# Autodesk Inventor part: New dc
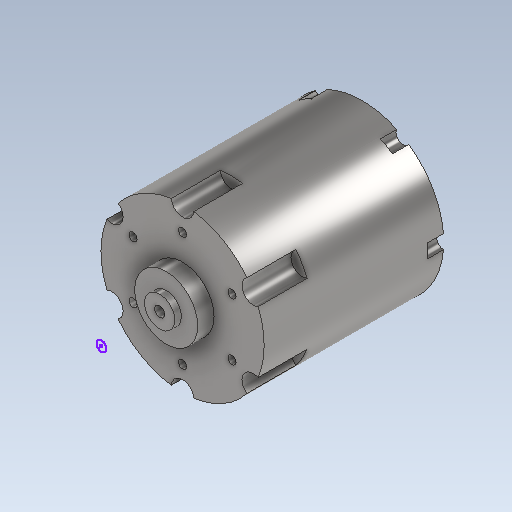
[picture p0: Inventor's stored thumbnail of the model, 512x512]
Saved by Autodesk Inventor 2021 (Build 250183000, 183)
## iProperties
Created: 2021-07
Part Number: New dc
Material: Steel, Mild
Document SubType Name: Sheet Metal
Designer: user
Density: 7.85 g/cm^3
Sheet Metal Rule: Default_mm
Appearance: Semi-Polished
Author: user
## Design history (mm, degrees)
sketch "Sketch1"
  geometry: C1 r 2.5 at (0, 0); 1 further point
  constraints: 1 centre point, 1 coincident
  dimensions: "d0" = 5 diameter of C1
extrude "Extrusion1" new body sketch "Sketch1" distance "d1" = 1.5; taper "d2" = 0 deg
sketch "Sketch2"
  geometry: C1 r 0.346 at (0, 2.5); C2 r 0.346 at (-2.165, 1.25); C3 r 0.346 at (-2.165, -1.25); C4 r 0.346 at (0, -2.5); C5 r 0.346 at (2.165, -1.25); C6 r 0.346 at (2.165, 1.25); 2 further points
  constraints: 6 centre point, 1 vertical alignment, 14 other
  dimensions: "d5" = 360 deg dimension on point (0, 0) C1.centre (derived)
cut "Cut1" sketch "Sketch2" dims "d8" = 0.5 (= Thickness), "d9" = 0
sketch "Sketch3"
  geometry: C1 r 0.125 at (0, 1.751); C2 r 0.125 at (1.516, 0.875); C3 r 0.125 at (1.516, -0.875); C4 r 0.125 at (0, -1.751); C5 r 0.125 at (-1.516, -0.875); C6 r 0.125 at (-1.516, 0.875); 1 further point
  constraints: 6 centre point, 13 other
  dimensions: "d10" = 0.25 diameter of C1; "d13" = 360 deg dimension on point (0, 0) C1.centre (derived)
cut "Cut2" sketch "Sketch3" dims "d7" = 0.5 (= Thickness), "d15" = 0.5 (= Thickness), "d16" = 0, "GapSize" = 0.5 (= Thickness), "SeamGap" = 0.01, "Thickness" = 0.5, "BendRadius" = 0.5 (= Thickness), "MinimumRemnant" = 1 (= 2 x Thickness), "BendReliefDepth" = 0.25 (= 0.5 x Thickness), "BendReliefWidth" = 0.5 (= Thickness), "CornerReliefSize" = 2 (= 4 x Thickness), "JacobiRadiusSize" = 0.5 (= BendRadius), "TransitionRadius" = 0.5 (= BendRadius)
sketch "Sketch4"
  geometry: C1 r 0.965 at (0, 0); 1 further point
  constraints: 1 centre point, 1 coincident
extrude "Extrusion2" join sketch "Sketch4" distance "d17" = 0.5; taper "d18" = 0 deg
sketch "Sketch5"
  geometry: C1 r 0.465 at (0, 0); 1 further point
  constraints: 1 centre point, 1 coincident
extrude "Extrusion3" join sketch "Sketch5" distance "d19" = 0.2; taper "d20" = 0 deg
sketch "Sketch6"
  geometry: C1 r 0.155 at (0, 0); 1 further point
  constraints: 1 centre point, 1 coincident
extrude "Extrusion4" join sketch "Sketch6" distance "d21" = 1.8; taper "d22" = 0 deg
sketch "Sketch7"
  geometry: C1 r 0.155 at (0, 0) reference; C2 r 2.5 at (0, 0); 1 further point
  constraints: 1 centre point, 1 coincident
extrude "Extrusion5" join sketch "Sketch7" distance "d23" = 2; taper "d24" = 0 deg
sketch "Sketch8"
  geometry: C1 r 0.155 at (0, 0) reference; C2 r 2.5 at (0, 0); 1 further point
  constraints: 1 centre point, 1 coincident
extrude "Extrusion6" join sketch "Sketch8" distance "d25" = 2; taper "d26" = 0 deg
sketch "Sketch9"
  geometry: C1 r 0.213 at (2.5, 0); C2 r 0.213 at (1.25, 2.165); C3 r 0.213 at (-1.25, 2.165); C4 r 0.213 at (-2.5, 0); C5 r 0.213 at (-1.25, -2.165); C6 r 0.213 at (1.25, -2.165); 2 further points
  constraints: 6 centre point, 1 horizontal alignment, 14 other
  dimensions: "d29" = 360 deg dimension on point (0, 0) C1.centre (derived)
cut "Cut3" sketch "Sketch9" dims "d31" = 0.5 (= Thickness), "d32" = 0
sketch "Sketch10"
  geometry: C1 r 0.945 at (0, 0); 1 further point
  constraints: 1 centre point, 1 coincident
extrude "Extrusion7" join sketch "Sketch10" distance "d33" = 0.5; taper "d34" = 0 deg
sketch "Sketch11"
  geometry: C1 r 0.25 at (0, 0); 1 further point
  constraints: 1 centre point, 1 coincident
  dimensions: "d35" = 0.5 diameter of C1
extrude "Extrusion8" join sketch "Sketch11" distance "d36" = 1; taper "d37" = 0 deg
sketch "Sketch12"
  geometry: 1 further point
sketch "Sketch13"
  geometry: C1 r 0.155 at (0, 0)
  constraints: 1 centre point
sketch "Sketch14"
  geometry: 1 further point
sketch "Sketch16"
  geometry: 1 further point
cut "Cut4" dims "d38" = 0.5 (= Thickness), "d39" = 0
body "Solid1"
